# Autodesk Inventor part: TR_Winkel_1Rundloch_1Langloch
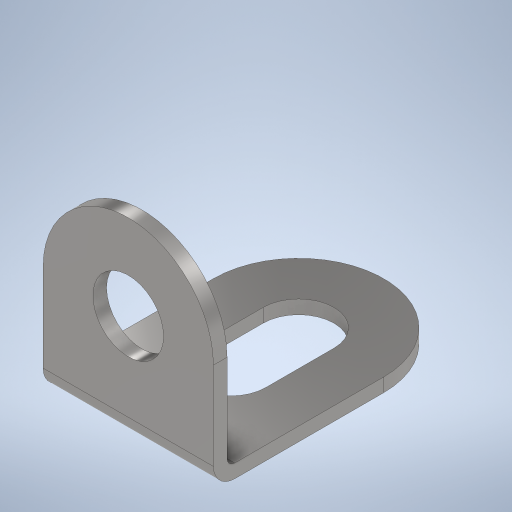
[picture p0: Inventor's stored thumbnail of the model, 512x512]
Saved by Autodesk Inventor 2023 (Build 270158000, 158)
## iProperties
Created: 2023-11
Part Number: TR_Winkel_1Rundloch_1Langloch
Material: Edelstahl
Document SubType Name: Modeling
Designer: Administrator
Density: 8 g/cm^3
Appearance: Halbpoliert
Author: Administrator
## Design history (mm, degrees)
sketch "Skizze1"
  geometry: L1 (1.25, 0)-(11.4, 0); L2 (11.4, 0)-(11.4, -0.8); L3 (11.4, -0.8)-(1.25, -0.8); L4 (0.8, -1.25)-(0.8, -15); L5 (0.8, -15)-(0, -15); L6 (0, -15)-(0, -1.25); A1 r 1.25 centre (1.25, -1.25) between (1.25, 0) and (0, -1.25); A2 r 0.45 centre (1.25, -1.25) between (1.25, -0.8) and (0.8, -1.25); 1 further point
  constraints: 12 end point, 5 perpendicular, 4 point on circle, 4 tangent, 2 centre point, 2 point on line, 1 coincident, 1 horizontal
  dimensions: "d0" = 1.25 radius of A1; "d2" = 0.8 distance between parallel lines of L3 L1 (= Dicke); "d3" = 11.4 distance of point (0, 0) L1.end; "d4" = 15 distance of point (0, 0) L5.end
extrude "Extrusion1" new body sketch "Skizze1" stored distance "d5" = 10 (= Einheitsmaß); taper "d6" = 0 deg
fillet "Rundung1" dims "d7" = 5 (= 0.5 x Einheitsmaß)
sketch "Skizze2"
  geometry: L1 (5, 8.75)-(5, 4.75); L2 (2.925, 8.75)-(2.925, 4.75); L3 (7.075, 4.75)-(7.075, 8.75); L4 (10, -1.25)-(0, -1.25) reference; A1 r 2.075 centre (5, 8.75) between (7.075, 8.75) and (2.925, 8.75); A2 r 2.075 centre (5, 4.75) between (2.925, 4.75) and (7.075, 4.75); 4 further points
  constraints: 8 end point, 4 point on circle, 4 tangent, 2 centre point, 1 horizontal alignment, 1 midpoint, 1 parallel, 1 vertical, 1 vertical alignment
  dimensions: "d9" = 4.15 diameter of A2 (= 2 x Radius); "d10" = 4 distance of L1.start L1.end
extrude "Extrusion2" cut sketch "Skizze2" extent not by distance; stored distance "d11" = 0; taper "d12" = 0 deg
sketch "Skizze3"
  geometry: C1 r 2.075 at (5, 5.15); A1 r 5 centre (5, 5.15) between (10, 5.15) and (0, 5.15) reference; 1 further point
  constraints: 1 centre point, 1 coincident
  dimensions: "d13" = 4.15 diameter of C1 (= 2 x Radius)
extrude "Extrusion3" cut sketch "Skizze3" extent not by distance; stored distance "d14" = 0; taper "d15" = 0 deg
node "Volumenkörper1"
other parameters: "Einheitsmaß" = 10 [user parameter; used in 2 equation terms], "Radius" = 2.075 [user parameter; used in 2 equation terms], "Fasen" = 0.5 [user parameter], "Dicke" = 0.8 [user parameter; used in 1 equation term], "Breitloch" = 2 [user parameter], "Langloch" = 32 [user parameter], "AchteckUmkreis" = 6 [user parameter], "DAchsAufnahme" = 4.1 [user parameter], "AchsDurchmesser" = 4 [user parameter], "AchsFase" = 0.5 [user parameter]
